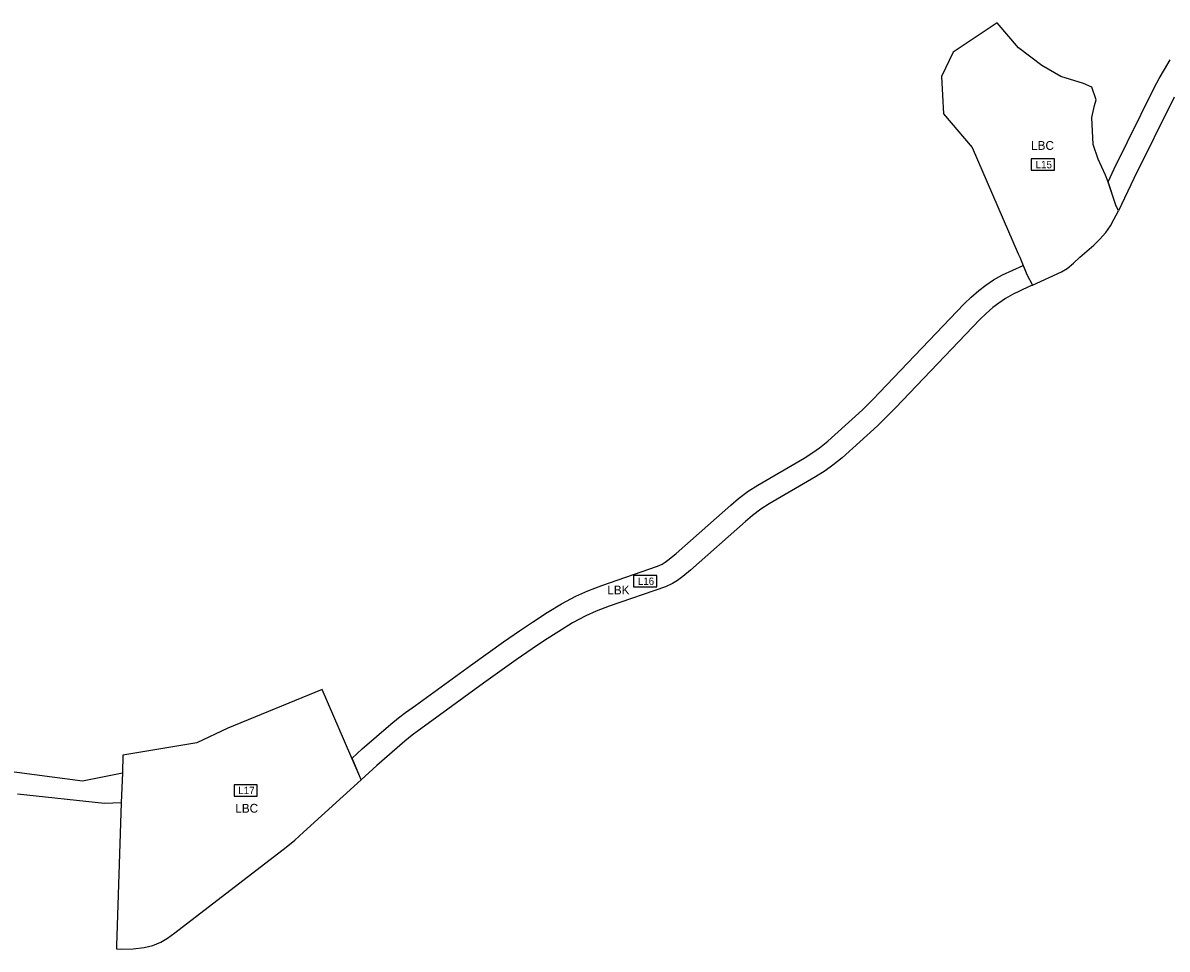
# Model space of a CAD drawing. Extents: x -546680 to -530218, y -1046521 to -1035695.
# Drawn here: x -545119 to -543557, y -1045026 to -1043761 of the extents above; entities that cross this region are included whole.
import ezdxf

# ---------------------------------------------------------------- set-up
doc = ezdxf.new("R2010")
doc.units = 0
for name, color, linetype in [('Vrstva 3', 7, 'Continuous'), ('Vrstva 32', 7, 'Continuous'), ('Vrstva 33', 7, 'Continuous'), ('Vrstva 54', 7, 'Continuous')]:
    doc.layers.add(name, color=color, linetype=linetype)

msp = doc.modelspace()

# ---------------------------------------------------------------- linework, layer by layer
at = {"layer": 'Vrstva 32'}
for points in [[(-543627, -1044010), (-543638, -1043977), (-543641, -1043969), (-543651, -1043947), (-543658, -1043927), (-543660, -1043890), (-543656, -1043874), (-543654, -1043866), (-543660, -1043849), (-543671, -1043844), (-543702, -1043834), (-543728, -1043819), (-543760, -1043795), (-543789, -1043761), (-543849, -1043801), (-543865, -1043834), (-543862, -1043885), (-543823, -1043931), (-543760.1, -1044076.3)], [(-543623.6, -1044017.7), (-543627, -1044010)], [(-543748.5, -1044104.8), (-543740.7, -1044119.2), (-543701, -1044100.9), (-543693.6, -1044096.3), (-543684.9, -1044088.9), (-543676.1, -1044081.1), (-543657, -1044064.6), (-543649.4, -1044057), (-543640.7, -1044047.1), (-543634.5, -1044038.1), (-543629.7, -1044029.6), (-543623.6, -1044017.7)], [(-543760.1, -1044076.3), (-543758, -1044081), (-543748.5, -1044104.8)], [(-544670.8, -1044761.7), (-544710, -1044671), (-544839, -1044724), (-544881, -1044744), (-544982, -1044761), (-544982.8, -1044784.8), (-544984.3, -1044826), (-544991, -1045021), (-544991, -1045025.5), (-544983.3, -1045025.7), (-544968.1, -1045025.1), (-544952.9, -1045023.5), (-544941.4, -1045020.8), (-544930.3, -1045016.1), (-544921.3, -1045010.9), (-544911.4, -1045003.3), (-544759.1, -1044886.6), (-544747.4, -1044877), (-544735.6, -1044866.1), (-544657, -1044794.4), (-544659, -1044789), (-544670.8, -1044761.7)]]:
    msp.add_lwpolyline(points, dxfattribs=at)
at = {"layer": 'Vrstva 33'}
for points in [[(-543547.4, -1043862.6), (-543602.3, -1043973.4), (-543623.6, -1044017.7), (-543627, -1044010), (-543637.7, -1043977.9), (-543629.3, -1043960.2), (-543574.1, -1043849), (-543567.8, -1043837), (-543560.8, -1043824.8), (-543552.8, -1043811.6)], [(-543753.6, -1044092.1), (-543748.5, -1044104.8), (-543740.7, -1044119.2), (-543746, -1044121.6), (-543768.1, -1044131.8), (-543777.8, -1044137.3), (-543786.9, -1044143.5), (-543795.1, -1044149.7), (-543804.1, -1044157.7), (-543812.5, -1044165.8), (-543927.8, -1044286.5), (-543936.8, -1044295.9), (-543952.1, -1044311), (-544000.6, -1044355.1), (-544013.2, -1044365.1), (-544023.8, -1044372.7), (-544036.7, -1044380.9), (-544100.1, -1044417.6), (-544111.6, -1044425), (-544122.9, -1044433.6), (-544132.4, -1044442), (-544207.5, -1044508.4), (-544217.9, -1044517), (-544225, -1044522.3), (-544232, -1044526.6), (-544241.8, -1044530.9), (-544318.4, -1044557.3), (-544336.1, -1044564.1), (-544350.4, -1044570.6), (-544368.5, -1044580.4), (-544387.2, -1044591.8), (-544406.6, -1044604.3), (-544423.6, -1044615.7), (-544445.3, -1044630.8), (-544490.1, -1044662.7), (-544565.4, -1044717.5), (-544578.7, -1044727), (-544587.3, -1044733.5), (-544597.2, -1044741.7), (-544635.5, -1044774.8), (-544657, -1044794.4), (-544659, -1044789), (-544669.3, -1044765.1), (-544655.5, -1044752.4), (-544616.5, -1044718.7), (-544605.9, -1044710), (-544596.5, -1044702.8), (-544582.9, -1044693.1), (-544507.6, -1044638.4), (-544462.6, -1044606.3), (-544440.6, -1044590.9), (-544423.1, -1044579.2), (-544403.1, -1044566.3), (-544383.5, -1044554.4), (-544363.8, -1044543.7), (-544347.7, -1044536.4), (-544328.6, -1044529.1), (-544252.7, -1044503), (-544245.9, -1044500), (-544241.9, -1044497.5), (-544236.5, -1044493.4), (-544227, -1044485.6), (-544152.3, -1044419.4), (-544141.9, -1044410.4), (-544128.9, -1044400.4), (-544115.8, -1044392), (-544052.3, -1044355.2), (-544040.5, -1044347.8), (-544031.3, -1044341.1), (-544020, -1044332.2), (-543972.7, -1044289.2), (-543958.2, -1044274.9), (-543949.4, -1044265.7), (-543833.8, -1044144.7), (-543824.6, -1044135.7), (-543814.1, -1044126.4), (-543804.3, -1044119.1), (-543793.8, -1044111.9), (-543781.9, -1044105.1), (-543753.6, -1044092.1)], [(-545234, -1044770), (-545037, -1044796), (-544982.8, -1044784.8), (-544984.3, -1044826), (-545007, -1044827), (-545126, -1044814)]]:
    msp.add_lwpolyline(points, dxfattribs=at)
at = {"layer": 'Vrstva 54'}
for points in [[(-543742.4, -1043946.7), (-543742.4, -1043962.3), (-543710.7, -1043962.3), (-543710.7, -1043946.7), (-543742.4, -1043946.7)], [(-544285.1, -1044515.6), (-544285.1, -1044531.2), (-544253.4, -1044531.2), (-544253.4, -1044515.6), (-544285.1, -1044515.6)], [(-544830.4, -1044801.2), (-544830.4, -1044816.7), (-544798.7, -1044816.7), (-544798.7, -1044801.2), (-544830.4, -1044801.2)]]:
    msp.add_lwpolyline(points, dxfattribs=at)

# ---------------------------------------------------------------- texts
at = {"layer": 'Vrstva 3'}
for s, p in [('LBC', (-543742.7, -1043934.4)), ('LBK', (-544321, -1044541.4)), ('LBC', (-544828.7, -1044839.4))]:
    msp.add_text(s, height=12, dxfattribs=at).set_placement(p)
at = {"layer": 'Vrstva 54'}
for s, p in [('L15', (-543736.5, -1043959.5)), ('L16', (-544279.4, -1044528.4)), ('L17', (-544824.6, -1044814))]:
    msp.add_text(s, height=10, dxfattribs=at).set_placement(p)

doc.saveas('drawing.dxf')
